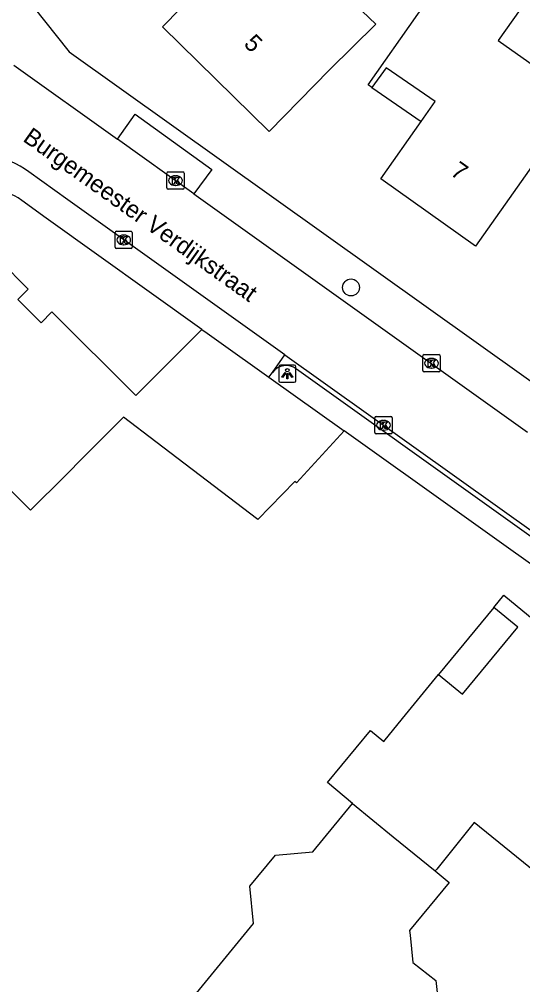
# Model space of a CAD drawing. Extents: x 159503 to 160347, y 382525 to 383272.
# Drawn here: x 160004 to 160033.2, y 383011.2 to 383067.2 of the extents above; entities that cross this region are included whole.
import ezdxf

# ---------------------------------------------------------------- set-up
doc = ezdxf.new("R2010")
doc.units = 0
for name, color, linetype in [('IMGEO_Boom', 7, 'Continuous'), ('IMGEO_Kolk', 7, 'Continuous'), ('IMGEO_Lichtpunt', 7, 'Continuous'), ('IMGEO_Openbare_ruimte_label', 7, 'Continuous'), ('IMGEO_Pand', 7, 'Continuous'), ('IMGEO_Pand_nummerreeks', 7, 'Continuous'), ('IMGEO_Pand_overbouw', 7, 'Continuous'), ('IMGEO_Rijbaan_lokaal_open', 7, 'Continuous'), ('IMGEO_Voetpad_open', 7, 'Continuous')]:
    doc.layers.add(name, color=color, linetype=linetype)

msp = doc.modelspace()

# ---------------------------------------------------------------- linework, layer by layer
at = {"layer": 'IMGEO_Boom'}
msp.add_circle((160023.229, 383051.672), 0.489, dxfattribs=at)
at = {"layer": 'IMGEO_Kolk'}
for p, q in [((160012.542, 383057.443), (160012.542, 383058.295)), ((160012.617, 383058.369), (160013.469, 383058.369)), ((160013.543, 383058.295), (160013.543, 383057.443)), ((160013.03, 383058.149), (160013.055, 383058.149)), ((160013.469, 383057.369), (160012.617, 383057.369)), ((160013.053, 383057.589), (160013.028, 383057.589)), ((160009.534, 383054.002), (160009.534, 383054.854)), ((160009.609, 383054.928), (160010.461, 383054.928)), ((160010.535, 383054.854), (160010.535, 383054.002)), ((160010.022, 383054.708), (160010.047, 383054.708)), ((160010.461, 383053.928), (160009.609, 383053.928)), ((160010.045, 383054.148), (160010.02, 383054.148)), ((160027.395, 383046.846), (160027.395, 383047.698)), ((160027.47, 383047.772), (160028.322, 383047.772)), ((160027.883, 383047.552), (160027.908, 383047.552)), ((160028.396, 383047.698), (160028.396, 383046.846)), ((160027.906, 383046.992), (160027.881, 383046.992)), ((160028.322, 383046.772), (160027.47, 383046.772)), ((160024.612, 383043.254), (160024.612, 383044.106)), ((160024.687, 383044.18), (160025.539, 383044.18)), ((160025.1, 383043.96), (160025.125, 383043.96)), ((160025.613, 383044.106), (160025.613, 383043.254)), ((160025.539, 383043.18), (160024.687, 383043.18)), ((160025.123, 383043.4), (160025.098, 383043.4))]:
    msp.add_line(p, q, dxfattribs=at)
for points in [[(160012.542, 383057.443), (160012.542, 383058.295)], [(160012.617, 383058.369), (160013.469, 383058.369)], [(160013.543, 383058.295), (160013.543, 383057.443)], [(160012.863, 383058.069), (160012.986, 383058.069), (160012.986, 383057.918), (160013.116, 383058.069), (160013.28, 383058.069), (160013.134, 383057.918), (160013.287, 383057.669), (160013.135, 383057.669), (160013.05, 383057.833), (160012.986, 383057.766), (160012.986, 383057.669), (160012.863, 383057.669), (160012.863, 383058.069)], [(160013.469, 383057.369), (160012.617, 383057.369)], [(160009.534, 383054.002), (160009.534, 383054.854)], [(160009.609, 383054.928), (160010.461, 383054.928)], [(160010.535, 383054.854), (160010.535, 383054.002)], [(160009.855, 383054.628), (160009.978, 383054.628), (160009.978, 383054.477), (160010.108, 383054.628), (160010.272, 383054.628), (160010.126, 383054.477), (160010.279, 383054.228), (160010.127, 383054.228), (160010.042, 383054.392), (160009.978, 383054.325), (160009.978, 383054.228), (160009.855, 383054.228), (160009.855, 383054.628)], [(160010.461, 383053.928), (160009.609, 383053.928)], [(160027.395, 383046.846), (160027.395, 383047.698)], [(160027.47, 383047.772), (160028.322, 383047.772)], [(160028.396, 383047.698), (160028.396, 383046.846)], [(160027.716, 383047.472), (160027.839, 383047.472), (160027.839, 383047.321), (160027.969, 383047.472), (160028.133, 383047.472), (160027.987, 383047.321), (160028.14, 383047.072), (160027.988, 383047.072), (160027.903, 383047.236), (160027.839, 383047.169), (160027.839, 383047.072), (160027.716, 383047.072), (160027.716, 383047.472)], [(160028.322, 383046.772), (160027.47, 383046.772)], [(160024.612, 383043.254), (160024.612, 383044.106)], [(160024.687, 383044.18), (160025.539, 383044.18)], [(160024.933, 383043.88), (160025.056, 383043.88), (160025.056, 383043.729), (160025.186, 383043.88), (160025.35, 383043.88), (160025.204, 383043.729), (160025.357, 383043.48), (160025.205, 383043.48), (160025.12, 383043.644), (160025.056, 383043.577), (160025.056, 383043.48), (160024.933, 383043.48), (160024.933, 383043.88)], [(160025.613, 383044.106), (160025.613, 383043.254)], [(160025.539, 383043.18), (160024.687, 383043.18)]]:
    msp.add_lwpolyline(points, dxfattribs=at)
for centre, start, end in [((160012.619, 383058.293), 91.552, 178.448), ((160012.619, 383058.293), 91.552, 178.448), ((160013.467, 383058.293), 1.552, 88.448), ((160013.467, 383058.293), 1.552, 88.448), ((160012.619, 383057.445), 181.552, 268.448), ((160012.619, 383057.445), 181.552, 268.448), ((160013.467, 383057.445), 271.552, 358.448), ((160013.467, 383057.445), 271.552, 358.448), ((160009.611, 383054.852), 91.552, 178.448), ((160009.611, 383054.852), 91.552, 178.448), ((160010.459, 383054.852), 1.552, 88.448), ((160010.459, 383054.852), 1.552, 88.448), ((160009.611, 383054.004), 181.552, 268.448), ((160009.611, 383054.004), 181.552, 268.448), ((160010.459, 383054.004), 271.552, 358.448), ((160010.459, 383054.004), 271.552, 358.448), ((160027.472, 383047.696), 91.552, 178.448), ((160027.472, 383047.696), 91.552, 178.448), ((160028.32, 383047.696), 1.552, 88.448), ((160028.32, 383047.696), 1.552, 88.448), ((160027.472, 383046.848), 181.552, 268.448), ((160027.472, 383046.848), 181.552, 268.448), ((160028.32, 383046.848), 271.552, 358.448), ((160028.32, 383046.848), 271.552, 358.448), ((160024.689, 383044.104), 91.552, 178.448), ((160024.689, 383044.104), 91.552, 178.448), ((160025.537, 383044.104), 1.552, 88.448), ((160025.537, 383044.104), 1.552, 88.448), ((160024.689, 383043.256), 181.552, 268.448), ((160024.689, 383043.256), 181.552, 268.448), ((160025.537, 383043.256), 271.552, 358.448), ((160025.537, 383043.256), 271.552, 358.448)]:
    msp.add_arc(centre, 0.0765, start, end, dxfattribs=at)
for centre, major_axis, ratio, start_param, end_param in [((160013.029, 383057.869), (-0.387, 0.002), 0.722429, 4.712389, 7.853982), ((160013.054, 383057.869), (-0.39, 0.002), 0.717154, 1.570796, 4.712389), ((160010.021, 383054.428), (-0.387, 0.002), 0.722429, 4.712389, 7.853982), ((160010.046, 383054.428), (-0.39, 0.002), 0.717154, 1.570796, 4.712389), ((160027.882, 383047.272), (-0.387, 0.002), 0.722429, 4.712389, 7.853982), ((160027.907, 383047.272), (-0.39, 0.002), 0.717154, 1.570796, 4.712389), ((160025.099, 383043.68), (-0.387, 0.002), 0.722429, 4.712389, 7.853982), ((160025.124, 383043.68), (-0.39, 0.002), 0.717154, 1.570796, 4.712389)]:
    msp.add_ellipse(centre, major_axis=major_axis, ratio=ratio, start_param=start_param, end_param=end_param, dxfattribs=at)
at = {"layer": 'IMGEO_Lichtpunt'}
for p, q in [((160019.033, 383047.069), (160019.033, 383046.262)), ((160019.033, 383047.069), (160019.033, 383046.262)), ((160019.935, 383047.164), (160019.127, 383047.164)), ((160019.935, 383047.164), (160019.127, 383047.164)), ((160020.029, 383046.262), (160020.029, 383047.069)), ((160020.029, 383046.262), (160020.029, 383047.069)), ((160019.127, 383046.168), (160019.935, 383046.168)), ((160019.127, 383046.168), (160019.935, 383046.168))]:
    msp.add_line(p, q, dxfattribs=at)
for points in [[(160019.407, 383046.733), (160019.446, 383046.705), (160019.258, 383046.443), (160019.22, 383046.47), (160019.407, 383046.733)], [(160019.509, 383046.685), (160019.556, 383046.685), (160019.556, 383046.363), (160019.509, 383046.363), (160019.509, 383046.685)], [(160019.619, 383046.705), (160019.657, 383046.732), (160019.844, 383046.47), (160019.805, 383046.442), (160019.619, 383046.705)]]:
    msp.add_lwpolyline(points, dxfattribs=at)
msp.add_circle((160019.532, 383046.867), 0.0994, dxfattribs=at)
for centre, start, end in [((160019.127, 383047.069), 90, 180), ((160019.127, 383047.069), 90, 180), ((160019.935, 383047.069), 0, 90), ((160019.935, 383047.069), 0, 90), ((160019.127, 383046.262), 180, 270), ((160019.127, 383046.262), 180, 270), ((160019.935, 383046.262), 270, 0), ((160019.935, 383046.262), 270, 360)]:
    msp.add_arc(centre, 0.0946, start, end, dxfattribs=at)
at = {"layer": 'IMGEO_Pand'}
for points in [[(160020.124, 383071.356), (160021.809, 383073.069), (160024.568, 383075.873), (160020.5, 383079.875), (160017.742, 383077.071), (160016.56, 383075.87), (160013.053, 383072.305), (160015.426, 383069.997), (160012.296, 383066.782), (160018.479, 383060.723), (160021.981, 383064.293), (160024.677, 383066.95), (160022.671, 383068.85), (160020.124, 383071.356)], [(160031.769, 383065.99), (160036.505, 383062.644), (160033.333, 383058.153), (160030.448, 383054.068), (160024.953, 383057.978), (160027.292, 383061.298), (160028.107, 383062.455), (160025.273, 383064.419), (160024.441, 383063.269), (160024.22, 383063.429), (160027.105, 383067.514), (160030.074, 383071.719), (160033.905, 383069.012), (160031.769, 383065.99)], [(160022.835, 383043.344), (160020.072, 383040.329), (160019.964, 383040.406), (160017.822, 383038.215), (160011.897, 383042.713), (160010.015, 383044.143), (160009.617, 383043.744), (160007.725, 383041.846), (160006.635, 383040.752), (160004.632, 383038.743), (160000, 383043.36), (159996.487, 383046.861), (160000, 383050.386), (160002.833, 383053.227), (160004.499, 383051.579), (160003.888, 383050.973), (160005.247, 383049.625), (160005.857, 383050.259), (160010.742, 383045.406), (160014.563, 383049.24)], [(160014.563, 383049.24), (160014.874, 383049.018), (160015.563, 383048.527), (160018.45, 383046.469)], [(160018.45, 383046.469), (160022.835, 383043.344)], [(160023.316, 383021.728), (160021.873, 383022.947), (160024.36, 383025.976), (160025.133, 383025.341), (160026.217, 383026.661), (160028.311, 383029.211), (160029.702, 383028.068), (160032.906, 383031.97), (160031.514, 383033.112), (160032.091, 383033.815), (160036.496, 383030.197), (160036.787, 383030.552), (160041.176, 383026.947), (160036.522, 383021.279), (160037.05, 383020.899), (160034.268, 383017.48), (160030.383, 383020.626), (160028.201, 383017.92), (160028.12, 383017.82)], [(160028.12, 383017.82), (160028.927, 383017.161), (160026.624, 383014.376), (160026.663, 383014.101), (160026.82, 383012.513), (160028.146, 383011.474), (160028.232, 383010.766), (160027.306, 383009.661), (160026.619, 383009.6), (160026.258, 383009.888), (160021.143, 383003.663), (160017.28, 383006.838), (160013.564, 383009.891), (160017.577, 383014.775), (160017.364, 383016.942), (160018.837, 383018.735), (160021.015, 383018.927), (160023.316, 383021.728)], [(160023.316, 383021.728), (160025.684, 383019.808), (160028.12, 383017.82)]]:
    msp.add_lwpolyline(points, dxfattribs=at)
at = {"layer": 'IMGEO_Pand_overbouw'}
for points in [[(160025.273, 383064.419), (160024.441, 383063.269), (160027.292, 383061.298), (160028.107, 383062.455)], [(160032.906, 383031.97), (160031.514, 383033.112), (160028.311, 383029.211), (160029.702, 383028.068)]]:
    msp.add_lwpolyline(points, close=True, dxfattribs=at)
at = {"layer": 'IMGEO_Rijbaan_lokaal_open'}
for points in [[(159969.339, 383112.369), (160000, 383073.962), (160006.879, 383065.344), (160051.214, 383033.728), (160053.92, 383031.798)], [(160003.656, 383064.565), (160009.676, 383060.27)], [(160009.676, 383060.27), (160010.696, 383061.715), (160015.146, 383058.518), (160014.112, 383057.105)], [(160014.112, 383057.105), (160009.676, 383060.27)], [(160019.394, 383047.76), (160006.786, 383056.747), (160004.528, 383058.374)], [(160014.112, 383057.105), (160033.481, 383043.284)], [(160019.394, 383047.76), (160044.075, 383030.167)]]:
    msp.add_lwpolyline(points, dxfattribs=at)
msp.add_arc((160001.877, 383054.948), 4.332, 52.2681, 83.9672, dxfattribs=at)
at = {"layer": 'IMGEO_Voetpad_open'}
for points in [[(160014.563, 383049.24), (160005.532, 383055.682), (160004.122, 383056.716)], [(160018.667, 383046.741), (160019.394, 383047.76)], [(160018.45, 383046.469), (160018.667, 383046.741)], [(160043.641, 383030.088), (160020.065, 383046.938)], [(160042.909, 383029.031), (160022.835, 383043.344)]]:
    msp.add_lwpolyline(points, dxfattribs=at)
for centre, radius, start, end in [((160002.667, 383054.832), 2.38, 52.3124, 149.6789), ((160019.465, 383046.139), 0.999, 53.0878, 142.9543)]:
    msp.add_arc(centre, radius, start, end, dxfattribs=at)

# ---------------------------------------------------------------- texts
at = {"layer": 'IMGEO_Openbare_ruimte_label'}
msp.add_text('Burgemeester Verdijkstraat', height=1, rotation=324.529, dxfattribs=at).set_placement((160004.128, 383060.197))
at = {"layer": 'IMGEO_Pand_nummerreeks'}
for s, rotation, p in [('5', 315.5786, (160016.955, 383065.745)), ('7', 324.566, (160028.938, 383058.236))]:
    msp.add_text(s, height=1, rotation=rotation, dxfattribs=at).set_placement(p)

doc.saveas('drawing.dxf')
